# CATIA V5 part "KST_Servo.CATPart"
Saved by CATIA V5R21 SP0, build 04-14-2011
Part number: KST_Servo
Bounding box of the stored display mesh (mm): x -6.75 to 47.25, y -10.5 to 10.5, z -41.2 to 5.5
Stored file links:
  F:\教程\Robotic_Arm_Arduino_Kinect\机械臂CAD\Arm_Detailed_Design\KST_Servo.CATPart
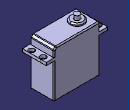
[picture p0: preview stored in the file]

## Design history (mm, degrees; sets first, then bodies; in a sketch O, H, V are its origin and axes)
Body1 (main body)
  Sketch1 on xy-plane, origin (0, 0, 0), H (1, 0, 0), V (0, 1, 0)
    line L1 (0, 10.5) -> (40.5, 10.5)
    line L2 (40.5, 10.5) -> (40.5, -10.5)
    line L3 (40.5, -10.5) -> (0, -10.5)
    line L4 (0, -10.5) -> (0, 10.5)
    length L1 = 40.5
    length L2 = 21
    distance L1 H = 10.5
    horizontal: L1 H, L3 H
    vertical: L2 V, L4 V
    coincidence: L4 V
  Pad1: profile Sketch1, direction (0, 0, -1), length 41.2
  Fillet1: radius 1, on face of Pad1 from Sketch1.L2; face of Pad1 from Sketch1.L4; start face of Pad1; end face of Pad1
  Sketch2 on face of Pad1 from Sketch1.L3, origin (0, -10.5, 0), H (1, 0, 0), V (0, 0, 1)
    point P1 (38.5, 0)
    line L1 (38.5, 0) -> (40.5, 0)
    line L2 (40.5, 0) -> (40.5, -2)
    line L3 (40.5, -2) -> (38.5, 0)
    reference projected line E1 (40.5, -1) -> (40.5, -40.2) from edge [face of Fillet1 | face of Pad1 from Sketch1.L2]
    angle L3 L1 = 45
    length L1 = 2
    distance L2 E1 = 0
    coincidence: P1 H
    horizontal: L1 H
    vertical: L2 V
  Pocket1: profile Sketch2, direction (0, 1, 0), through (limit type 6)
  Fillet2: radius 1, on face of Pocket1 from Sketch2.L3
  Plane1: type Offset, RefPlane end face of Pad1, Offset 31.2
  Sketch3 on Plane1, origin (0, 0, -10), H (1, 0, 0), V (0, 1, 0)
    line L1 (-6.75, 10.5) -> (47.25, 10.5)
    line L2 (47.25, 10.5) -> (47.25, -10.5)
    line L3 (47.25, -10.5) -> (-6.75, -10.5)
    line L4 (-6.75, -10.5) -> (-6.75, 10.5)
    reference intersected line E1 (0, 10.5) -> (40.5, 10.5) from face of Pad1 from Sketch1.L1
    reference intersected line E2 (40.5, -10.5) -> (0, -10.5) from face of Pad1 from Sketch1.L3
    reference projected line E3 (40.5, -9.5) -> (40.5, 9.5) from edge [face of Pad1 from Sketch1.L2 | face of Fillet2]
    distance L4 L2 = 54
    distance E3 L2 = 6.75
    horizontal: L1 H, L3 H
    vertical: L2 V
    coincidence: L1 E1, L3 E2
  Pad2: profile Sketch3, direction (0, 0, 1), length 2.5
  Sketch4 on end face of Pad2, origin (0, 0, -7.5), H (1, 0, 0), V (0, 1, 0)
    circle A1 centre (44.5, 5) radius 2.5
    point P1 (44.5, 5)
    reference projected line E1 (47.25, -10.5) -> (47.25, 10.5) from edge [face of Pad2 from Sketch3.L2 | end face of Pad2]
    circle A2 centre (44.5, -5) radius 2.5
    point P2 (44.5, -5)
    reference projected line E2 (47.25, -10.5) -> (47.25, 10.5) from edge [face of Pad2 from Sketch3.L2 | end face of Pad2]
    circle A3 centre (-4, 5) radius 2.5
    point P3 (-4, 5)
    circle A4 centre (-4, -5) radius 2.5
    point P4 (-4, -5)
    reference projected line E3 (-6.75, 10.5) -> (-6.75, -10.5) from edge [face of Pad2 from Sketch3.L4 | end face of Pad2]
    reference projected line E4 (-6.75, 10.5) -> (-6.75, -10.5) from edge [face of Pad2 from Sketch3.L4 | end face of Pad2]
    radius A1 = 2.5
    distance P1 E1 = 2.75
    radius A2 = 2.5
    distance P1 P2 = 10
    distance P1 H = 5
    distance E2 P2 = 2.75
    radius A4 = 2.5
    radius A3 = 2.5
    distance P3 P4 = 10
    distance P3 E3 = 2.75
    distance P4 E4 = 2.75
    distance P3 H = 5
  Pocket2: profile Sketch4, direction (0, 0, -1), through (limit type 6)
Body2
  Sketch5 on start face of Pad1, origin (0, 0, 0), H (1, 0, 0), V (0, 1, 0)
    circle A1 centre (9.66, 0) radius 6
    point P1 (9.66, 0)
    reference projected line E1 (0, 9.5) -> (0, -9.5) from edge [face of Pad1 from Sketch1.L4 | face of Fillet1]
    distance E1 P1 = 9.66
    radius A1 = 6
    coincidence: P1 H
  Pad3: profile Sketch5, direction (0, 0, 1), length 2
  Chamfer1: length 1, angle 45, on end face of Pad3
  Sketch6 on end face of Pad3, origin (0, 0, 2), H (1, 0, 0), V (0, 1, 0)
    circle A1 centre (9.66, 0) radius 2.5
    point P1 (9.66, 0)
    reference projected circle E1 centre (9.66, 0) radius 5 from edge [face of Chamfer1 | end face of Pad3]
    radius A1 = 2.5
    coincidence: P1 H
    concentricity: A1 E1
  Pad4: profile Sketch6, direction (0, 0, 1), length 3.5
